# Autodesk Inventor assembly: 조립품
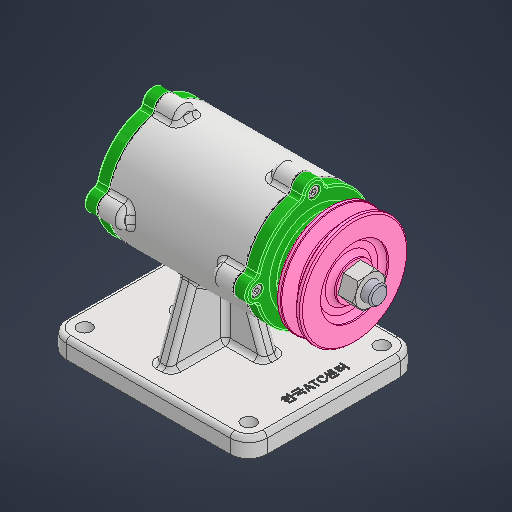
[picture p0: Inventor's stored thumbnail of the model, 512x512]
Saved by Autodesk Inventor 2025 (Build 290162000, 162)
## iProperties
Created: 2025-08
Part Number: 조립품
Document SubType Name: Assembly
Designer: infra10
Author: infra10
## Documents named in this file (12)
- C:\Users\infra10\Desktop\750806V1005\조립품.iam
- C:\Users\infra10\Desktop\공용부품_20250118_2 (1)\V-벨트풀리\V-벨트풀리.ipt
- C:\Users\infra10\Desktop\공용부품_20250118_2 (1)\개스킷\개스킷.ipt
- C:\Users\infra10\Desktop\공용부품_20250118_2 (1)\너트 M12 x 1.25\너트 M12 x 1.25.ipt
- C:\Users\infra10\Desktop\공용부품_20250118_2 (1)\뒤커버\뒤커버.ipt
- C:\Users\infra10\Desktop\공용부품_20250118_2 (1)\베어링 6204\베어링 6204.ipt
- C:\Users\infra10\Desktop\750806V1005\본체.ipt
- C:\Users\infra10\Desktop\공용부품_20250118_2 (1)\볼트 M4 x 12\볼트 M4 x 12.ipt
- C:\Users\infra10\Desktop\공용부품_20250118_2 (1)\앞커버\앞커버.ipt
- C:\Users\infra10\Desktop\공용부품_20250118_2 (1)\오일 실\오일 실.ipt
- C:\Users\infra10\Desktop\공용부품_20250118_2 (1)\축\축.ipt
- C:\Users\infra10\Desktop\공용부품_20250118_2 (1)\키 4 x 4\키 4 x 4.ipt
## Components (3 placed, 2 different names)
1. V-벨트풀리:1
2. 개스킷:1
3. 개스킷:2
